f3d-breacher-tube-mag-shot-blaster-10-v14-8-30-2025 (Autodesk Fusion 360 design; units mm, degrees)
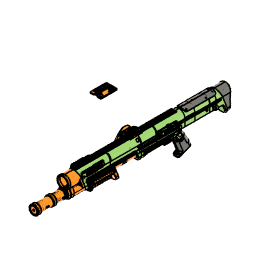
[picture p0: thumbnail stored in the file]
named bodies: "LIFTER Silly Shell - Dummy Model", "Shell Tube 13 inches long", "Drum Spring", "OLDOLD dummy follower for modeling", "FollowerRoller (Print 3 of these)_FBsprings", "Silly Shell - Dummy Model (1)", "Silly Shell - Dummy Model (2)", "Silly Shell - Dummy Model (3)", "Silly Shell - Dummy Model (4)", "M3X20 screw", "9452K87 -123 o-ring (1)", "Nylon spacer 94639A205", "#4 3/8in long Screw 90434A177_Steel Flat Head Thread-Forming Screws for Plastic", "CUTTER TOOL 4-40 - #4 - m3x10 flat head", "Longer CUTTER TOOL 4-40 - #4 - m3x10 flat head", "GripBody_WithShoe", "Trigger", "PlungerRod", "SearArm", "Nylon spacer 94639A205 (1)", "M3X16 screw (1)", "LifterRoller", "POM bearing 623 3*10*4mm", "Ball Bearing Printed Dummy Roller for Priming", "POM bearing 623 3*10*4mm (1)", "M3X12 screw", "POM bearing 623 3*10*4mm (2)", "GripPanel_Right", "FrontPTcover", "M3X50 screw", "M3X25 screw (1)", "M3X16 screw (2)", "Drum Spring (1)", "Drum Spring (2)", "FollowerRoller (Print 3 of these)_FBsprings (2)", "FollowerRoller (Print 3 of these)_FBsprings (1)", "M3X16 screw (3)", "M3X16 screw (4)", "Extension spring dummy", "Extension spring dummy max safe extension", "TriggerGuard", "Small Spring - 9657K644 (3)", "small spring dummy spacing (1)", "smiley face", "smiley face (1)", "smiley face (2)", "M3 cutting tool", "M3X20 screw (10)", "Catch", "small spring dummy spacing", "Small Spring - 9657K644", "small spring dummy spacing (2)", "Small Spring - 9657K644 (6)", "M3X12 screw (2)", "(8  long 8-32 thread) Threaded Rod", "M3X12 screw (2) (1)", "Small Spring - 9657K644 (4)", "Small Spring - 9657K644 (5)", "M3X25 screw (2)", "9637K26_5.5"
